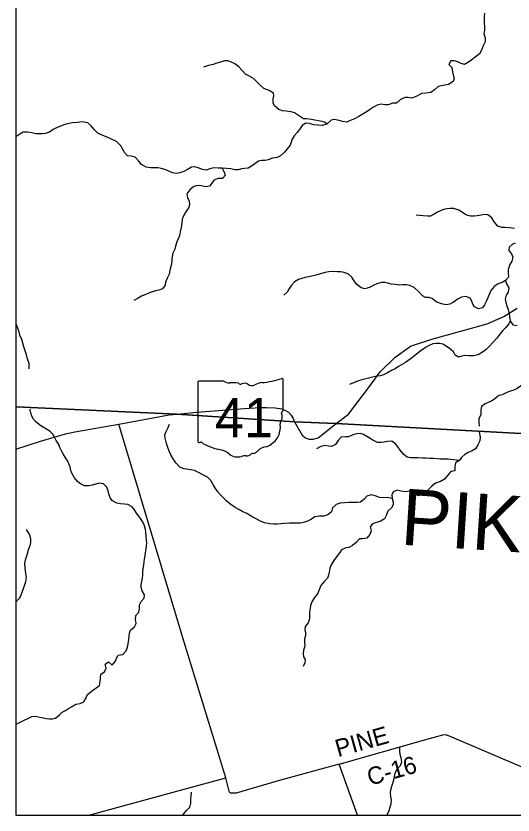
# Model space of a CAD drawing. Extents: x -139 to 835, y 0 to 440.
# Drawn here: x 373.2 to 426.3, y 185.1 to 270.4 of the extents above; entities that cross this region are included whole.
import ezdxf

# ---------------------------------------------------------------- set-up
doc = ezdxf.new("R2010")
doc.units = 0
for name, color, linetype in [('Default', 7, 'Continuous'), ('GM_X_County_Road', 7, 'Continuous'), ('GM_X_County_Road_Text', 7, 'Continuous'), ('GM_X_County_Text', 7, 'Continuous'), ('GM_X_Minor_River', 7, 'Continuous'), ('GM_X_State_Location', 7, 'Continuous'), ('GM_X_State_Route', 7, 'Continuous'), ('GM_X_State_Shield', 7, 'Continuous'), ('GM_X_Township_Road', 7, 'Continuous'), ('SH_Cut_Line', 7, 'Continuous')]:
    doc.layers.add(name, color=color, linetype=linetype)

msp = doc.modelspace()

# ---------------------------------------------------------------- linework, layer by layer
at = {"layer": 'Default'}
msp.add_lwpolyline([(373.24, 306.128), (373.24, 228.621), (390.412, 227.867), (402.968, 227.036), (407.389, 226.858), (433.728, 225.419), (479.461, 222.215), (494.743, 221.147), (512.652, 220.106), (533.705, 218.461), (553.865, 217.083)], dxfattribs=at)
msp.add_lwpolyline([(373.24, 228.621), (373.24, 185.075), (509.507, 185.075), (512.652, 220.106), (494.743, 221.147), (479.461, 222.215), (433.728, 225.419), (407.389, 226.858), (402.968, 227.036), (390.412, 227.867)], close=True, dxfattribs=at)
at = {"layer": 'GM_X_County_Road'}
for points in [[(409.674, 185.075), (407.729, 190.508), (401.237, 188.706), (396.735, 187.419), (396.264, 187.416), (396.107, 187.422), (395.973, 187.621), (395.645, 189.044), (391.031, 203.968), (384.206, 226.783)], [(407.729, 190.508), (416.734, 193.08), (418.79, 193.617), (419.041, 193.654), (419.453, 193.54), (427.529, 190.066), (428.437, 189.666), (429.238, 189.452), (431.361, 189.276), (435.253, 189.374), (435.985, 189.354), (437.671, 189.078), (438.839, 188.895), (439.339, 188.429), (439.97, 187.993), (440.642, 187.567), (441.046, 187.285), (441.426, 186.8), (442.484, 185.075)]]:
    msp.add_lwpolyline(points, dxfattribs=at)
at = {"layer": 'GM_X_Minor_River'}
for points in [[(423.236, 270.638), (423.192, 270.302), (423.188, 269.966), (423.208, 269.546), (423.23, 269.246), (423.251, 268.886), (423.18, 268.431), (423.305, 268.033), (423.312, 267.601), (423.07, 267.1), (422.962, 266.765), (422.708, 266.325), (422.246, 265.946), (421.89, 265.674), (421.547, 265.426), (421.1, 265.156), (420.75, 265.292), (420.4, 265.464), (419.997, 265.553), (419.658, 265.557), (419.431, 265.188), (419.765, 264.848), (419.824, 264.379), (419.885, 264.078), (420.01, 263.669), (419.902, 263.358), (419.415, 263.052), (419.022, 262.973), (418.656, 262.905), (418.303, 262.838), (417.907, 262.482), (417.498, 262.187), (416.988, 262.097), (416.505, 262.067), (416.006, 261.797), (415.495, 261.587), (415.104, 261.64), (414.765, 261.656), (414.266, 261.422), (413.843, 261.031), (413.465, 261.048), (412.954, 260.874), (412.615, 260.866), (412.225, 260.955), (411.78, 260.828), (411.399, 260.605), (411.057, 260.393), (410.701, 260.146), (410.175, 259.828), (409.846, 259.628), (409.294, 259.323), (408.914, 259.183), (408.534, 259.02), (408.091, 259.097), (407.598, 259.247), (407.194, 259.3), (406.867, 259.232), (406.418, 258.818), (405.96, 258.679), (405.452, 258.686), (405.022, 258.727), (404.541, 258.865), (404.164, 258.905), (403.795, 258.646), (403.569, 258.337), (403.25, 257.909), (402.932, 257.564), (402.731, 257.195), (402.61, 256.884), (402.501, 256.574)], [(406.418, 258.818), (406.277, 259), (405.927, 259.088), (405.536, 259.153), (405.12, 259.242), (404.782, 259.294), (404.261, 259.36), (403.922, 259.377), (403.496, 259.658), (402.979, 260), (402.616, 260.113), (402.069, 260.179), (401.692, 260.244), (401.289, 260.381), (400.825, 260.747), (400.699, 261.073), (400.692, 261.505), (400.749, 261.816), (400.714, 262.129), (400.249, 262.41), (399.677, 262.598), (399.253, 262.987), (398.958, 263.339), (398.584, 263.679), (398.08, 263.962), (397.743, 264.134), (397.384, 264.523), (397.011, 264.911), (396.586, 265.253), (396.223, 265.437), (395.86, 265.55), (395.482, 265.555), (395.063, 265.428), (394.683, 265.325), (394.29, 265.186), (393.793, 265.06), (393.256, 264.898)], [(402.501, 256.574), (402.169, 256.158), (401.891, 255.825), (401.468, 255.41), (401.113, 255.258), (400.617, 255.192), (400.145, 255.006), (399.818, 254.914), (399.479, 254.93), (399.113, 254.863), (398.718, 254.568), (398.375, 254.308), (398.02, 254.108), (397.628, 254.065), (397.302, 254.033), (396.948, 253.941), (396.596, 253.946), (396.154, 254.023), (395.712, 254.089), (395.256, 254.118), (394.825, 254.111), (394.356, 254.129), (393.924, 254.038), (393.544, 253.887), (393.141, 253.964), (392.7, 254.15), (392.31, 254.25), (391.971, 254.207), (391.55, 253.984), (391.156, 253.76), (390.723, 253.598), (390.357, 253.53), (389.941, 253.619), (389.565, 253.78), (389.112, 253.966), (388.735, 254.09), (388.397, 254.13), (388.006, 254.147), (387.615, 254.152), (387.12, 254.218), (386.642, 254.488), (386.36, 254.864), (385.962, 255.277), (385.52, 255.39), (385.129, 255.431), (384.835, 255.783), (384.618, 256.158), (384.414, 256.497), (383.952, 256.959), (383.447, 257.217), (382.98, 257.403), (382.5, 257.589), (381.969, 257.847), (381.597, 258.236), (381.263, 258.613), (380.903, 258.953), (380.291, 259.045), (379.821, 258.99), (379.273, 258.937), (378.907, 258.882), (378.449, 258.779), (378.003, 258.604), (377.57, 258.406), (377.202, 258.218), (376.807, 257.947), (376.4, 257.796), (376.074, 257.775), (375.735, 257.756), (375.343, 257.772), (374.941, 257.873), (374.459, 257.963), (373.99, 257.957), (373.66, 257.721), (373.24, 257.459)], [(395.256, 254.118), (395.471, 253.671), (395.57, 253.322), (395.292, 253.001), (394.823, 253.007), (394.351, 252.845), (394.151, 252.511), (393.885, 252.202), (393.532, 252.123), (392.999, 252.213), (392.595, 252.266), (392.203, 252.163), (391.78, 251.796), (391.461, 251.38), (391.546, 250.934), (391.711, 250.632), (391.77, 250.199), (391.661, 249.841), (391.395, 249.508), (391.168, 249.102), (390.992, 248.66), (390.935, 248.289), (390.862, 247.785), (390.764, 247.306), (390.68, 246.887), (390.558, 246.552), (390.423, 246.242), (390.273, 245.776), (390.177, 245.453), (389.988, 245.023), (389.918, 244.687), (389.887, 244.352), (389.828, 243.872), (389.719, 243.513), (389.662, 243.19), (389.591, 242.794), (389.376, 242.365), (389.214, 241.958), (389.17, 241.635), (388.877, 241.242), (388.484, 241.091), (388.144, 241.011), (387.606, 240.825), (387.055, 240.628), (386.623, 240.453), (386.267, 240.241), (385.833, 239.994)], [(426.432, 247.671), (425.924, 247.725), (425.455, 247.766), (425.103, 247.794), (424.674, 247.919), (424.289, 248.368), (424.008, 248.815), (423.595, 249.132), (423.23, 249.16), (422.877, 249.104), (422.445, 249.037), (422.118, 248.993), (421.753, 248.973), (421.324, 249.099), (420.988, 249.318), (420.483, 249.612), (419.951, 249.799), (419.572, 249.815), (419.023, 249.738), (418.683, 249.634), (418.223, 249.423), (417.868, 249.187), (417.474, 248.976), (417.147, 248.98), (416.678, 249.022), (416.313, 249.05), (415.962, 249.102)], [(426.528, 246.098), (426.2, 245.969), (425.857, 245.673), (425.839, 245.338), (426.134, 244.95), (426.26, 244.625), (426.149, 244.194), (425.936, 243.837), (425.759, 243.287), (425.754, 242.963), (425.787, 242.471), (425.469, 242.126), (425.581, 241.765), (425.823, 241.33), (425.752, 240.875), (425.538, 240.542), (425.454, 240.135), (425.514, 239.762), (425.627, 239.401), (425.752, 239.039), (425.839, 238.726), (425.912, 238.317), (425.984, 237.825), (426.278, 237.401), (426.72, 237.312)], [(425.469, 242.126), (425.179, 241.926), (424.707, 241.763), (424.285, 241.492), (423.914, 241.041), (423.726, 240.635), (423.55, 240.205), (423.402, 239.883), (423.254, 239.524), (423.014, 239.191), (422.595, 239.112), (422.18, 239.297), (422.002, 239.611), (421.902, 239.912), (421.724, 240.238), (421.243, 240.424), (420.786, 240.357), (420.418, 240.157), (419.93, 239.791), (419.536, 239.592), (419.117, 239.513), (418.636, 239.626), (418.091, 239.849), (417.652, 240.19), (417.302, 240.314), (416.949, 240.318), (416.612, 240.478), (416.227, 240.915), (415.725, 241.365), (415.258, 241.598), (414.92, 241.65), (414.528, 241.643), (414.175, 241.611), (413.733, 241.688), (413.29, 241.742), (412.926, 241.83), (412.588, 241.894), (412.249, 241.898), (411.764, 241.772), (411.436, 241.62), (410.963, 241.385), (410.465, 241.235), (410.062, 241.324), (409.572, 241.714), (409.342, 242.089), (409.099, 242.464), (408.713, 242.792), (408.272, 242.978), (407.907, 243.042), (407.503, 243.059), (406.969, 243.065), (406.629, 243.045), (406.25, 242.966), (405.857, 242.862), (405.254, 242.69), (404.823, 242.587), (404.456, 242.495), (404.103, 242.427), (403.749, 242.336), (403.396, 242.22), (402.975, 241.961), (402.657, 241.616), (402.364, 241.2), (402.164, 240.878), (401.833, 240.57)], [(373.24, 237.54), (373.274, 237.442), (373.411, 237.066), (373.526, 236.737), (373.615, 236.337), (373.811, 235.855), (373.936, 235.467), (374.05, 235.079), (374.187, 234.644), (374.312, 234.209), (374.391, 233.915), (374.494, 233.598), (374.608, 233.28), (374.596, 232.676)], [(425.984, 237.825), (425.823, 237.502), (425.53, 237.11), (425.212, 236.79), (424.868, 236.386), (424.562, 235.957), (424.125, 235.506), (423.727, 235.079), (423.37, 234.735), (423.014, 234.463), (422.554, 234.193), (422.056, 234.09), (421.561, 234.096), (421.156, 234.125), (420.803, 234.045), (420.449, 233.953), (420.113, 234.149), (419.935, 234.511), (419.497, 234.876), (419.16, 235.096), (418.798, 235.316), (418.46, 235.392), (418.069, 235.409), (417.729, 235.377), (417.388, 235.225), (416.94, 234.954), (416.598, 234.73), (416.163, 234.399), (415.754, 234.08), (415.305, 233.725), (414.792, 233.383), (414.055, 232.936), (413.699, 232.7), (413.331, 232.524), (412.897, 232.277), (412.45, 232.042), (412.123, 231.938), (411.757, 231.906), (411.129, 231.782), (410.159, 231.505), (409.688, 231.367), (409.242, 231.204), (408.848, 231.016)], [(428.383, 232.013), (428.08, 231.837), (427.787, 231.42), (427.431, 231.1), (427.088, 230.828), (426.719, 230.604), (426.272, 230.393), (425.866, 230.278), (425.538, 230.126), (425.117, 229.915), (424.764, 229.847), (424.341, 229.48), (423.973, 229.256), (423.645, 229.104), (423.316, 228.964), (422.908, 228.656), (422.851, 228.321), (422.856, 227.805), (422.642, 227.363), (422.624, 227.015), (422.656, 226.559)], [(381.017, 220.213), (380.546, 220.213), (380.115, 220.405), (379.789, 220.657), (379.475, 221.066), (379.214, 221.546), (379.097, 221.858), (379.006, 222.243), (378.888, 222.555), (378.771, 222.856), (378.536, 223.204), (378.262, 223.624), (378.092, 223.937), (377.923, 224.285), (377.805, 224.61), (377.544, 225.042), (377.361, 225.402), (377.179, 225.703), (376.891, 226.015), (376.317, 226.375), (375.886, 226.627), (375.402, 226.987), (375.115, 227.312), (374.946, 227.648), (374.828, 227.997), (374.737, 228.321), (374.727, 228.385)], [(413.38, 218.856), (412.844, 218.976), (412.452, 218.94), (412.02, 218.963), (411.563, 219.155), (411.145, 219.239), (410.7, 219.094), (410.399, 218.794), (410.02, 218.481), (409.693, 218.445), (409.236, 218.433), (408.778, 218.432), (408.295, 218.408), (407.85, 218.36), (407.393, 218.227), (407.014, 217.854), (406.909, 217.446), (406.517, 217.097), (406.085, 216.965), (405.615, 216.952), (405.144, 216.892), (404.778, 216.651), (404.346, 216.447), (403.915, 216.278), (403.588, 216.23), (403.209, 216.218), (402.412, 216.217), (401.915, 216.169), (401.51, 216.144), (401.131, 216.132), (400.712, 216.132), (400.346, 216.167), (399.771, 216.263), (399.34, 216.431), (398.857, 216.695), (398.504, 216.875), (397.798, 217.282), (397.445, 217.438), (397.092, 217.63), (396.635, 217.894), (396.152, 218.23), (395.681, 218.614), (395.394, 218.915), (395.08, 219.251), (394.767, 219.575), (394.518, 219.923), (394.31, 220.295), (394.048, 220.764), (393.669, 221.148), (393.264, 221.352), (392.794, 221.604), (392.298, 221.844), (391.905, 221.915), (391.174, 222.011), (390.716, 222.191), (390.298, 222.659), (390.024, 223.092), (389.776, 223.5), (389.606, 223.836), (389.489, 224.197), (389.384, 224.509), (389.254, 224.857), (389.15, 225.29), (389.137, 225.638), (389.281, 226.011), (389.438, 226.347), (389.634, 226.792)], [(422.687, 225.971), (422.779, 225.397), (422.753, 225.001), (422.544, 224.568), (422.282, 224.16), (421.838, 223.895), (421.511, 223.763), (421.158, 223.558), (420.831, 223.282), (420.531, 222.898), (420.151, 222.669), (420.073, 222.225), (420.06, 221.804), (419.641, 221.72), (419.302, 221.323), (418.988, 220.927), (418.53, 220.674), (418.021, 220.482), (417.576, 220.145), (417.302, 219.845), (416.935, 219.484), (416.491, 219.207), (416.151, 219.123), (415.733, 219.351), (415.275, 219.627), (414.818, 219.566), (414.347, 219.638), (413.929, 219.746), (413.484, 219.565), (413.367, 219.253), (413.38, 218.856), (413.497, 218.472), (413.497, 218.172), (413.301, 217.872), (412.922, 217.499), (412.739, 217.03), (412.556, 216.67), (412.098, 216.393), (411.719, 216.309), (411.288, 216.164), (411.052, 215.816), (411.157, 215.42), (410.987, 215.023), (410.686, 214.638), (410.242, 214.554), (409.915, 214.542), (409.535, 214.169), (409.156, 213.856), (408.764, 213.64), (408.437, 213.592), (407.993, 213.387), (407.797, 213.075), (407.457, 212.63), (407.169, 212.221), (406.868, 211.788), (406.75, 211.428), (406.646, 210.983), (406.606, 210.659), (406.488, 210.359), (406.122, 209.986), (405.769, 209.577), (405.586, 209.097), (405.416, 208.688), (405.102, 208.279), (404.801, 207.811), (404.67, 207.414), (404.592, 206.957), (404.565, 206.645), (404.578, 206.333), (404.578, 205.996), (404.408, 205.6), (404.107, 205.191), (404.055, 204.891), (404.146, 204.518), (404.133, 204.218), (404.041, 203.882), (404.028, 203.545), (404.067, 203.101), (403.936, 202.656), (403.871, 202.26), (403.936, 201.96), (404.106, 201.66), (404.067, 201.299), (403.883, 200.927)], [(420.531, 222.898), (419.354, 223.053), (418.504, 223.052), (418.138, 223.076), (417.785, 223.111), (417.367, 223.135), (416.975, 223.147), (416.609, 223.171), (416.151, 223.182), (415.799, 223.182), (415.354, 223.194), (415.001, 223.277), (414.622, 223.541), (414.23, 223.997), (414.008, 224.37), (413.773, 224.67), (413.354, 224.982), (412.897, 224.933), (412.544, 224.861), (412.204, 224.824), (411.838, 224.836), (411.329, 225.064), (410.858, 225.364), (410.309, 225.676), (409.956, 225.784), (409.616, 225.76), (409.172, 225.639), (408.741, 225.447), (408.388, 225.422), (407.956, 225.386), (407.617, 225.037), (407.329, 224.629), (406.911, 224.4), (406.545, 224.448), (406.218, 224.52), (405.76, 224.412), (405.316, 224.147)], [(373.24, 194.752), (373.623, 194.934), (374.107, 195.187), (374.499, 195.379), (374.944, 195.572), (375.284, 195.609), (375.624, 195.561), (376.003, 195.477), (376.461, 195.382), (376.801, 195.346), (377.128, 195.346), (377.455, 195.419), (377.887, 195.756), (378.174, 196.069), (378.515, 196.225), (378.842, 196.442), (379.169, 196.622), (379.64, 196.911), (380.097, 196.984), (380.49, 197.153), (380.725, 197.574), (380.83, 197.886), (381.288, 198.283), (381.785, 198.632), (382.138, 198.897), (382.23, 199.33), (382.244, 199.714), (382.283, 200.123), (382.702, 200.351), (382.872, 200.736), (382.741, 201.181), (383.121, 201.433), (383.513, 201.073), (383.866, 201.506), (383.984, 201.819), (384.154, 202.119), (384.638, 202.216), (384.991, 202.601), (385.148, 202.973), (385.227, 203.358), (385.28, 203.815), (385.306, 204.187), (385.346, 204.488), (385.45, 204.788), (385.882, 205.161), (386.078, 205.522), (386, 205.942), (386.04, 206.363), (386.341, 206.736), (386.432, 207.168), (386.42, 207.493), (386.59, 207.877), (386.93, 208.202), (386.969, 208.563), (386.708, 209.007), (386.604, 209.343), (386.617, 209.668), (386.67, 210.004), (386.735, 210.377), (386.775, 210.677), (386.788, 210.978), (386.814, 211.374), (386.867, 211.723), (386.932, 212.083), (386.972, 212.396), (387.024, 212.72), (387.064, 213.057), (387.142, 213.489), (387.182, 213.79), (387.195, 214.102), (387.182, 214.426), (387.143, 214.787), (387.105, 215.256), (387.052, 215.556), (386.948, 215.94), (386.805, 216.277), (386.583, 216.613), (386.334, 216.961), (386.112, 217.285), (385.89, 217.658), (385.629, 217.982), (385.172, 218.198), (384.819, 218.234), (384.388, 218.269), (384.009, 218.353), (383.525, 218.617), (383.29, 218.917), (383.134, 219.362), (383.095, 219.662), (382.951, 220.059), (382.572, 220.407), (382.076, 220.503), (381.749, 220.394), (381.357, 220.286), (381.017, 220.213)], [(373.24, 207.707), (373.321, 207.945), (373.667, 208.25), (373.798, 208.567), (373.989, 209.153), (374.145, 209.575), (374.276, 209.997), (374.348, 210.407), (374.301, 210.841), (374.241, 211.145), (374.206, 211.45), (374.194, 211.93), (374.266, 212.305), (374.386, 212.727), (374.494, 213.102), (374.589, 213.407), (374.744, 213.829), (374.816, 214.146), (374.817, 214.544), (374.722, 214.954), (374.543, 215.258), (374.364, 215.551)], [(412.833, 185.075), (412.836, 185.093), (413.059, 185.562), (413.176, 185.959), (413.294, 186.271), (413.307, 186.679), (413.255, 187.016), (413.216, 187.448), (413.255, 187.748), (413.36, 188.145), (413.478, 188.565), (413.595, 188.974), (413.7, 189.526), (413.883, 189.935), (414.263, 190.344), (414.42, 190.752), (414.354, 191.173), (414.237, 191.533), (414.211, 191.917), (414.211, 192.314)], [(391.056, 185.075), (391.102, 185.151), (391.442, 185.572), (391.782, 185.92), (391.887, 186.329), (391.913, 186.75), (391.926, 187.122), (391.979, 187.506)]]:
    msp.add_lwpolyline(points, dxfattribs=at)
at = {"layer": 'GM_X_State_Route'}
for points in [[(407.397, 226.842), (408.713, 227.869), (410.843, 230.677), (412.096, 232.37), (413.673, 233.885), (415.34, 235.101), (417.619, 235.845), (420.565, 236.694), (423.51, 237.495), (425.292, 238.291), (426.736, 239.16)], [(390.42, 227.85), (392.542, 228.056), (394.868, 228.234), (398.081, 228.501), (399.419, 228.56), (399.977, 228.568), (400.902, 228.526), (401.561, 228.433), (401.945, 228.291), (402.339, 228.064), (402.604, 227.753), (402.806, 227.384), (402.975, 227.02)], [(373.24, 224.119), (375.853, 224.968), (378.514, 225.754), (379.509, 225.966), (384.206, 226.783), (389.604, 227.786), (390.42, 227.85)], [(402.975, 227.02), (403.766, 225.614), (404.123, 225.34), (404.485, 225.202), (404.962, 225.174), (405.479, 225.34), (407.397, 226.842)]]:
    msp.add_lwpolyline(points, dxfattribs=at)
at = {"layer": 'GM_X_State_Shield'}
for p, q in [((392.654, 231.281), (392.654, 224.953)), ((395.405, 231.389), (392.744, 231.389)), ((401.741, 228.236), (401.741, 231.546)), ((401.74, 228.237), (401.741, 228.236))]:
    msp.add_line(p, q, dxfattribs=at)
for centre, major_axis, start_param, end_param in [((392.758, 231.294), (0.105, 0), 1.712693, 3.28349), ((396.039, 232.124), (1.021, 0), 4.042523, 4.731795), ((396.377, 227.837), (3.666, 0), 1.404758, 1.657858), ((397.209, 231.327), (0.295, 0), 3.836095, 5.185415), ((397.642, 230.595), (0.612, 0), 0.950623, 2.079405), ((399.734, 229.457), (1.939, 0), 1.699011, 2.107814), ((398.504, 240.016), (9.637, 0), 4.814394, 5.042369), ((401.641, 231.56), (0.101, 0), 6.141152, 7.989035), ((398.432, 231.599), (0.737, 0), 4.081561, 5.145723), ((401.718, 227.993), (0.157, 0), 1.883978, 3.671073), ((400.722, 227.575), (0.94, 0), 5.934695, 6.695948), ((401.633, 228.223), (0.108, 0), 5.05454, 6.418171), ((402.104, 226.851), (0.684, 0), 2.387724, 3.262537), ((399.044, 226.43), (2.41, 0), 5.101752, 6.440018), ((392.759, 224.939), (0.106, 0), 3.00124, 4.508301), ((392.775, 225.587), (0.81, 0), 4.665946, 4.897461), ((392.941, 224.588), (0.292, 0), 0.519207, 1.627899), ((396.631, 230.273), (6.959, 0), 4.195997, 4.488961), ((400.061, 223.177), (1.32, 0), 1.647645, 2.488434), ((394.556, 222.11), (2.177, 0), 0.823519, 1.323587), ((396.911, 224.557), (1.382, 0), 4.026481, 4.996735), ((397.81, 224.083), (0.736, 0), 4.691044, 5.507374), ((398.476, 223.47), (0.207, 0), 1.147584, 2.315152), ((398.388, 224.34), (0.779, 0), 4.937069, 5.64225), ((397.709, 222.369), (1.135, 0), 1.495662, 1.94098)]:
    msp.add_ellipse(centre, major_axis=major_axis, ratio=0.917426, start_param=start_param, end_param=end_param, dxfattribs=at)
at = {"layer": 'GM_X_Township_Road'}
msp.add_lwpolyline([(381.028, 185.075), (390.81, 187.735), (395.645, 189.044)], dxfattribs=at)
at = {"layer": 'SH_Cut_Line'}
for points in [[(607.596, 213.413), (607.596, 400.079), (373.24, 400.079), (373.24, 228.621), (390.412, 227.867), (402.968, 227.036), (407.389, 226.858), (433.728, 225.419), (479.461, 222.215), (494.743, 221.147), (512.652, 220.106), (533.705, 218.461), (553.865, 217.083)], [(373.24, 228.621), (373.24, 185.075), (607.596, 185.075), (607.596, 213.413), (553.865, 217.083), (533.705, 218.461), (512.652, 220.106), (494.743, 221.147), (479.461, 222.215), (433.728, 225.419), (407.389, 226.858), (402.968, 227.036), (390.412, 227.867)]]:
    msp.add_lwpolyline(points, close=True, dxfattribs=at)

# ---------------------------------------------------------------- texts
at = {"layer": 'GM_X_County_Road_Text'}
for s, height, rotation, p in [('PINE', 1.8502, 15.63556, (407.605, 191.246)), ('C-16', 1.8506, 15.69327, (411.009, 188.191))]:
    msp.add_text(s, height=height, rotation=rotation, dxfattribs=at).set_placement(p)
at = {"layer": 'GM_X_County_Text'}
msp.add_text('PIKE COUNTY', height=6.00014, rotation=356.27066, dxfattribs=at).set_placement((414.193, 213.934))
at = {"layer": 'GM_X_State_Location'}
for s in ['s', 'r']:
    msp.add_text(s, height=0.00599, dxfattribs=at).set_placement((397.095, 227.696))
msp.add_text('41', height=0.00599, rotation=0.00001, dxfattribs=at).set_placement((395.452, 227.26))
at = {"layer": 'GM_X_State_Shield'}
msp.add_text('41', height=4.1684, dxfattribs=at).set_placement((394.471, 225.399))

doc.saveas('drawing.dxf')
